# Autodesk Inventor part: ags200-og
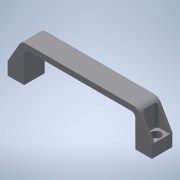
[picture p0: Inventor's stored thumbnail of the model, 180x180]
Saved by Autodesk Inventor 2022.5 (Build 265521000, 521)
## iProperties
Created: 2016-12
Part Number: ags200-og
Material: 一般
Document SubType Name: Modeling
Designer: imaocorp
Density: 1 g/cm^3
Appearance: 既定
Author: imaocorp
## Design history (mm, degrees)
node "ags200-og.x_t1"
node "ags200-og"
node "Base1"
